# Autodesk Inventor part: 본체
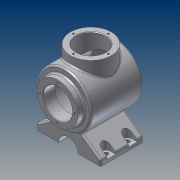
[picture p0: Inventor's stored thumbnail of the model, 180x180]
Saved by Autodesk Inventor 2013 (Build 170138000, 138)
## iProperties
Created: 2017-04
Part Number: 본체
Material: 알루미늄 6061
Document SubType Name: Modeling
Designer: Administrator
Density: 2.71 g/cm^3
Mass: 1670.75 g
Surface Area: 1066.86 cm^2
Volume: 616.514 cm^3
Author: Administrator
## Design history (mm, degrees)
sketch "스케치1"
  geometry: L1 (82, 62)-(82, -58); L2 (109, 62)-(120, 62); L3 (120, 62)-(120, 53); L4 (123, 50)-(129, 50); L5 (132, 47)-(132, -44.454); L6 (109, 62)-(109, 40); L7 (109, 40)-(119, 40); L8 (122, 37)-(122, -37.903); A1 r 113 centre (82, 55) between (82, -58) and (130.282, -47.166); A2 r 103 centre (82, 55) between (82, -48) and (120.11, -40.69); A3 r 3 centre (123, 53) between (120, 53) and (123, 50); A4 r 3 centre (129, 47) between (132, 47) and (129, 50); A5 r 3 centre (119, 37) between (122, 37) and (119, 40); A6 r 3 centre (119, -37.903) between (120.11, -40.69) and (122, -37.903); A7 r 3 centre (129, -44.454) between (130.282, -47.166) and (132, -44.454); 4 further points
  constraints: 16 end point, 16 point on circle, 10 tangent, 7 centre point, 6 point on line, 3 parallel, 3 perpendicular, 2 vertical, 1 horizontal alignment
  dimensions: "d0" = 120 distance of L1.end L1.start; "d3" = 82 distance from line of L1 point (0, 0); "d4" = 54 diameter of L6 L1; "d5" = 76 diameter of L3 L1; "d8" = 100 diameter of L5 L1; "d9" = 22 distance of L2.start L6.end; "d10" = 10 distance between parallel lines of L5 L8; "d11" = 113 radius of A1; "d12" = 10 radial gap between concentric circles of A1 A2; "d13" = 3 radius of A3; "d14" = 3 radius of A4; "d15" = 3 radius of A5; "d16" = 3 radius of A6; "d17" = 3 radius of A7; "d33" = 50 vertical distance of point (0, 0) L4.start; "d109" = 108 distance from line of L1.end L4
revolve "회전1" sketch "스케치1" stored, may be unused: angle "d18" = 90 deg
sketch "스케치2"
  geometry: L1 (60, 0)-(60, 10); L2 (60, 10)-(21.584, 36.899); L3 (-60, 0)-(-60, 10); L4 (-60, 10)-(-21.584, 36.899); L5 (18, 0)-(60, 0); L6 (-60, 0)-(-18, 0); A1 r 50 centre (0, 82) between (21.584, 36.899) and (-21.584, 36.899) reference; A2 r 18 centre (0, 0) between (18, 0) and (-18, 0); 2 further points
  constraints: 12 end point, 5 equal length, 4 point on circle, 2 coincident, 1 centre point, 1 horizontal, 1 perpendicular
  dimensions: "d23" = 36 diameter of A2; "d26" = 60 distance of L3.start point (0, 0); "d27" = 120 distance of L1.start L3.start; "d29" = 55 deg angle of L3 L4; "d102" = 10 distance of L1.end L1.start; "d110" = 82 vertical distance of A1.centre L3.start
extrude "돌출1" join sketch "스케치2" distance "d31" = 42; taper "d32" = 0 deg; dims "d103" = 38, "d104" = 0
node "작업 평면1"
sketch "스케치3"
  geometry: C1 r 38 at (0, 0); 1 further point
  constraints: 1 centre point, 1 coincident
  dimensions: "d35" = 76 diameter of C1
extrude "돌출2" join sketch "스케치3" stored distance "d36" = 80; taper "d37" = 0 deg
hole "구멍1" diameter "d40" = 54; stored, may be unused: countersink angle "d44" = 90 deg, drill point angle "d46" = 118 deg; dims "d38" = 10, "d39" = 10, "d41" = 6, "d42" = 4, "d43" = 2, "d45" = 8
sketch "스케치4"
  geometry: C1 r 38 at (0, 0) reference; 2 further points
  constraints: 1 vertical alignment
  dimensions: "d47" = 32.5 distance of point (0, 32.5) C1.centre
hole "구멍2" sketch "스케치4" at (0, 32.5) diameter "d48" = 3.242; stored, may be unused: countersink angle "d52" = 90 deg, drill point angle "d54" = 118 deg; dims "d49" = 8, "d50" = 4, "d51" = 2, "d53" = 10
sketch "스케치5"
  geometry: C1 r 27 at (0, 0) reference; 1 further point
  constraints: 1 vertical alignment
  dimensions: "d58" = 32.5 distance of point (0, 32.5) C1.centre
hole "구멍3" sketch "스케치5" at (0, 32.5) diameter "d59" = 3.242; stored, may be unused: countersink angle "d63" = 90 deg, drill point angle "d65" = 118 deg; dims "d60" = 8, "d61" = 4, "d62" = 2, "d64" = 10
node "작업 평면2"
sketch "스케치7"
  geometry: L1 (-60, -72)-(-60, -82) reference; C1 r 47 at (0, 0) reference; 2 further points
  constraints: 1 coincident, 1 other
feature "엠보싱1" sketch "스케치7" dims "d69" = 0.5, "d70" = 0
fillet "모깎기1" dims "d71" = 3
chamfer "모따기1" distance "d72" = 1; stored, may be unused: second distance "d73" = 2, angle "d74" = 45 deg
fillet "모깎기2" dims "d75" = 3
fillet "모깎기3" dims "d76" = 3
fillet "모깎기4" dims "d77" = 3
sketch "스케치8"
  geometry: L1 (-78, 77)-(-78, 3) reference; C1 r 4 at (32, 20); C2 r 4 at (-68, 20); C3 r 4 at (-68, 60); C4 r 4 at (32, 60); 4 further points
  constraints: 4 centre point, 3 equal radius, 2 horizontal alignment, 2 vertical alignment
  dimensions: "d78" = 8 diameter of C1; "d82" = 10 horizontal distance of point (42, 3) C1.centre; "d83" = 20 vertical distance of C1.centre point (39, 0); "d105" = 20 vertical distance of point (39, 80) C4.centre; "d106" = 10 horizontal distance of C2.centre L1.end
extrude "돌출3" cut sketch "스케치8" distance "d84" = 6; taper "d85" = 0 deg
sketch "스케치9"
  geometry: L1 (10, 57)-(10, -17) reference; L2 (10, 8)-(0, 8); L3 (0, -8)-(10, -8); L4 (-110.443, 20)-(10, 20); L5 (-68, 60)-(-32, 60) reference; L6 (-32, -20)-(-68, -20) reference; L7 (-50, 60)-(-50, -20); L8 (0, 48)-(10, 48); L9 (10, 32)-(0, 32); L10 (-110, 32)-(-100, 32); L11 (-100, 48)-(-110, 48); L12 (-110, 8)-(-100, 8); L13 (-100, -8)-(-110, -8); L14 (-110, -8)-(-110, 8); L15 (-110, 32)-(-110, 48); L16 (10, -8)-(10, 8); L17 (10, 32)-(10, 48); C1 r 4 at (0, 0) reference; A1 r 8 centre (0, 0) between (0, 8) and (0, -8); A2 r 8 centre (0, 40) between (0, 48) and (0, 32); A3 r 8 centre (-100, 40) between (-100, 32) and (-100, 48); A4 r 8 centre (-100, 0) between (-100, -8) and (-100, 8); 1 further point
  constraints: 28 end point, 15 symmetric about line, 8 point on circle, 4 centre point, 3 collinear, 3 midpoint, 3 perpendicular, 2 point on line, 2 tangent, 1 coincident, 1 horizontal, 3 other
  dimensions: "d86" = 8 radius of A1
extrude "돌출6" cut sketch "스케치9" stored distance "d107" = 10; taper "d108" = 0 deg
node "솔리드1"
pattern_circular "원형 패턴1" dims angle "d56" = 360 deg
pattern_circular "원형 패턴2" dims angle "d67" = 360 deg
other parameters: "d34" = 147, "d98" = 0.5, "d99" = 2, "d100" = 0
